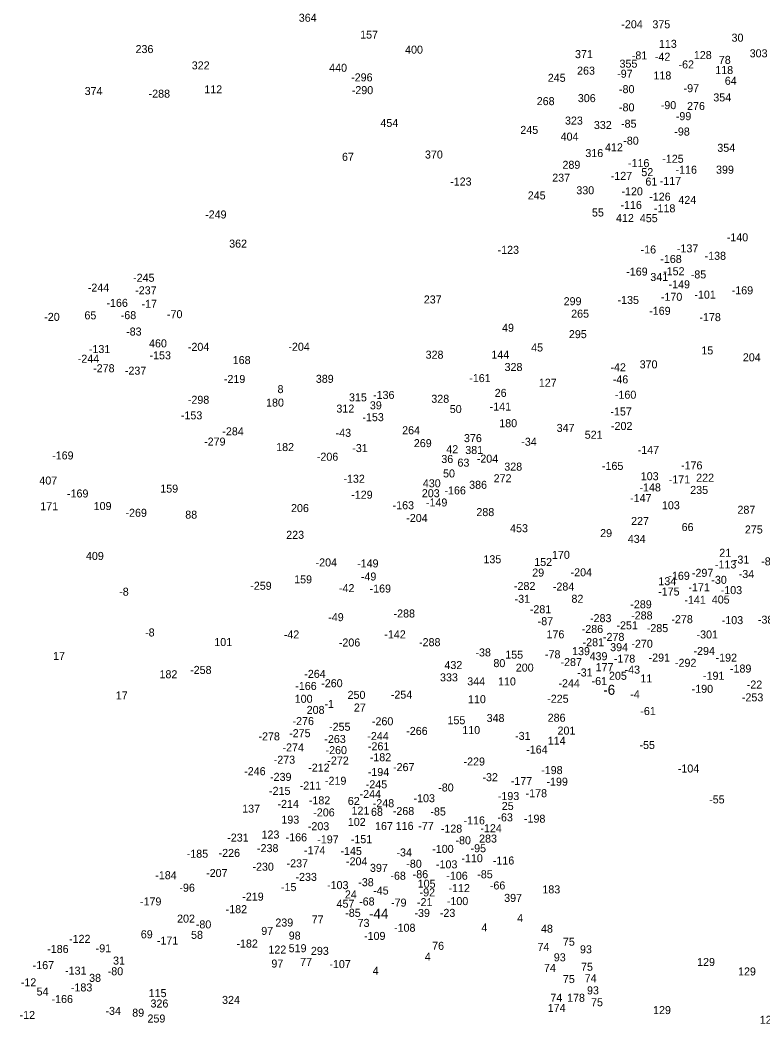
# Model space of a CAD drawing. Extents: x -784109 to -782312, y -974244 to -970866.
# Drawn here: x -783411 to -782876, y -973652 to -972930 of the extents above; entities that cross this region are included whole.
import ezdxf

# ---------------------------------------------------------------- set-up
doc = ezdxf.new("R2010")
doc.units = 0
doc.layers.add('Vrstva 24', color=7, linetype='Continuous')

msp = doc.modelspace()

# ---------------------------------------------------------------- texts
at = {"layer": 'Vrstva 24'}
for s, height, p in [('364', 5.76, (-783210.142, -972931.112)), ('-204', 5.76, (-782978.038, -972935.798)), ('375', 5.76, (-782955.695, -972935.832)), ('157', 5.76, (-783165.987, -972943.272)), ('30', 5.76, (-782898.749, -972945.472)), ('236', 5.76, (-783327.586, -972953.662)), ('400', 5.76, (-783133.642, -972954.082)), ('113', 5.76, (-782951.028, -972949.892)), ('371', 5.76, (-783011.377, -972957.292)), ('-81', 5.76, (-782970.508, -972958.198)), ('-42', 5.76, (-782953.917, -972959.17)), ('128', 5.76, (-782925.875, -972957.962)), ('78', 5.76, (-782907.905, -972961.422)), ('303', 5.76, (-782885.699, -972956.702)), ('322', 5.76, (-783287.163, -972965.402)), ('440', 5.76, (-783188.271, -972967.102)), ('355', 5.76, (-782979.353, -972964.152)), ('-62', 5.76, (-782936.887, -972964.714)), ('-296', 5.76, (-783172.478, -972974.024)), ('245', 5.76, (-783030.968, -972974.332)), ('263', 5.76, (-783009.896, -972969.182)), ('-97', 5.76, (-782981.043, -972971.402)), ('118', 5.76, (-782954.938, -972972.652)), ('118', 5.76, (-782910.468, -972968.742)), ('112', 5.76, (-783278.118, -972982.652)), ('-80', 5.76, (-782979.732, -972982.506)), ('-97', 5.76, (-782933.241, -972981.8)), ('64', 5.76, (-782903.602, -972976.472)), ('374', 5.76, (-783364.211, -972983.842)), ('-288', 5.76, (-783318.188, -972985.756)), ('-290', 5.76, (-783172.012, -972983.214)), ('306', 5.76, (-783009.353, -972988.952)), ('354', 5.76, (-782911.858, -972988.452)), ('268', 5.76, (-783038.926, -972991.132)), ('-80', 5.76, (-782979.726, -972995.558)), ('-90', 5.76, (-782949.682, -972993.988)), ('276', 5.76, (-782930.758, -972994.632)), ('-99', 5.76, (-782938.845, -973001.936)), ('454', 5.76, (-783151.404, -973006.832)), ('245', 5.76, (-783050.728, -973011.812)), ('323', 5.76, (-783018.593, -973005.112)), ('332', 5.76, (-782997.803, -973008.302)), ('-85', 5.76, (-782978.266, -973007.33)), ('404', 5.76, (-783021.721, -973016.642)), ('-98', 5.76, (-782939.931, -973013.002)), ('412', 5.76, (-782989.801, -973024.362)), ('-80', 5.76, (-782976.672, -973019.552)), ('354', 5.76, (-782908.978, -973024.702)), ('67', 5.76, (-783179.048, -973031.172)), ('370', 5.76, (-783119.351, -973029.532)), ('316', 5.76, (-783003.939, -973028.482)), ('-125', 5.76, (-782948.616, -973032.6)), ('289', 5.76, (-783020.406, -973036.932)), ('-116', 5.76, (-782973.256, -973035.712)), ('-116', 5.76, (-782939.048, -973040.482)), ('399', 5.76, (-782909.909, -973040.452)), ('237', 5.76, (-783027.775, -973046.202)), ('-127', 5.76, (-782985.683, -973044.9)), ('52', 5.76, (-782963.653, -973042.212)), ('-123', 5.76, (-783101.228, -973048.97)), ('330', 5.76, (-783010.439, -973055.262)), ('61', 5.76, (-782960.729, -973049.002)), ('-117', 5.76, (-782950.433, -973048.52)), ('245', 5.76, (-783045.378, -973058.972)), ('-120', 5.76, (-782977.968, -973056.04)), ('-126', 5.76, (-782957.99, -973059.88)), ('424', 5.76, (-782937.014, -973062.182)), ('-116', 5.76, (-782978.672, -973065.792)), ('-118', 5.76, (-782954.572, -973068.264)), ('-249', 5.76, (-783277.546, -973072.676)), ('55', 5.76, (-782999.173, -973071.252)), ('412', 5.76, (-782981.891, -973075.232)), ('455', 5.76, (-782964.728, -973075.332)), ('-140', 5.76, (-782902.196, -973089.126)), ('362', 5.76, (-783260.226, -973093.642)), ('-123', 5.76, (-783067.094, -973098.12)), ('-16', 5.76, (-782964.177, -973097.872)), ('-137', 5.76, (-782938.078, -973097.084)), ('-168', 5.76, (-782950.017, -973104.696)), ('-138', 5.76, (-782918.142, -973102.414)), ('-245', 5.76, (-783329.38, -973118.216)), ('-169', 5.76, (-782974.54, -973113.78)), ('341', 5.76, (-782957.191, -973117.652)), ('-152', 5.76, (-782947.978, -973113.526)), ('-85', 5.76, (-782928.095, -973115.81)), ('-244', 5.76, (-783361.966, -973125.324)), ('-237', 5.76, (-783327.859, -973127.258)), ('-149', 5.76, (-782944.059, -973122.93)), ('-169', 5.76, (-782898.638, -973127.254)), ('237', 5.76, (-783120.185, -973133.822)), ('-135', 5.76, (-782980.768, -973134.186)), ('-170', 5.76, (-782949.606, -973131.934)), ('-101', 5.76, (-782925.488, -973130.36)), ('-166', 5.76, (-783348.538, -973136.294)), ('-17', 5.76, (-783323.284, -973136.962)), ('299', 5.76, (-783019.559, -973135.092)), ('-169', 5.76, (-782958.022, -973142.012)), ('-20', 5.76, (-783393.296, -973146.356)), ('65', 5.76, (-783364.366, -973145.242)), ('-68', 5.76, (-783338.254, -973145.124)), ('-70', 5.76, (-783304.962, -973144.422)), ('265', 5.76, (-783014.146, -973144.052)), ('-178', 5.76, (-782921.876, -973146.552)), ('49', 5.76, (-783063.892, -973154.182)), ('-83', 5.76, (-783334.373, -973156.898)), ('295', 5.76, (-783015.786, -973158.782)), ('-131', 5.76, (-783361.19, -973169.52)), ('460', 5.76, (-783317.879, -973165.412)), ('-204', 5.76, (-783289.951, -973167.919)), ('-204', 5.76, (-783217.621, -973167.833)), ('45', 5.76, (-783042.938, -973168.392)), ('15', 5.76, (-782920.455, -973170.502)), ('-244', 5.76, (-783369.184, -973176.47)), ('-153', 5.76, (-783317.544, -973174.03)), ('168', 5.76, (-783257.669, -973177.442)), ('328', 5.76, (-783118.873, -973173.582)), ('144', 5.76, (-783071.567, -973173.542)), ('204', 5.76, (-782890.615, -973175.482)), ('-278', 5.76, (-783358.108, -973183.31)), ('-237', 5.76, (-783335.285, -973185.05)), ('328', 5.76, (-783062.053, -973182.442)), ('-42', 5.76, (-782985.908, -973182.632)), ('370', 5.76, (-782964.871, -973180.512)), ('-219', 5.76, (-783264.038, -973191.055)), ('389', 5.76, (-783197.876, -973190.942)), ('-161', 5.76, (-783087.484, -973190.414)), ('-46', 5.76, (-782984.218, -973191.334)), ('8', 5.76, (-783225.423, -973198.362)), ('127', 5.76, (-783037.407, -973193.732)), ('-298', 5.76, (-783289.967, -973206.006)), ('315', 5.76, (-783174.025, -973204.272)), ('-136', 5.76, (-783156.696, -973202.535)), ('328', 5.76, (-783114.763, -973205.302)), ('26', 5.76, (-783069.176, -973201.052)), ('-160', 5.76, (-782982.69, -973202.37)), ('180', 5.76, (-783233.682, -973208.042)), ('312', 5.76, (-783183.075, -973212.362)), ('39', 5.76, (-783158.976, -973209.992)), ('50', 5.76, (-783101.499, -973212.682)), ('-141', 5.76, (-783072.778, -973210.894)), ('-153', 5.76, (-783294.976, -973217.216)), ('-153', 5.76, (-783164.377, -973218.541)), ('-157', 5.76, (-782985.92, -973214.444)), ('264', 5.76, (-783135.752, -973227.952)), ('180', 5.76, (-783065.882, -973222.872)), ('347', 5.76, (-783024.591, -973226.272)), ('-202', 5.76, (-782985.502, -973224.872)), ('-284', 5.76, (-783265.149, -973228.736)), ('-43', 5.76, (-783183.634, -973229.797)), ('376', 5.76, (-783091.288, -973233.612)), ('521', 5.76, (-783004.395, -973231.182)), ('-279', 5.76, (-783278.279, -973236.096)), ('182', 5.76, (-783226.405, -973240.052)), ('-31', 5.76, (-783171.647, -973240.779)), ('269', 5.76, (-783127.349, -973237.212)), ('42', 5.76, (-783103.988, -973241.582)), ('381', 5.76, (-783090.345, -973242.152)), ('-34', 5.76, (-783050.038, -973236.218)), ('-147', 5.76, (-782966.27, -973242.089)), ('-169', 5.76, (-783387.614, -973246.07)), ('-206', 5.76, (-783197.141, -973246.989)), ('36', 5.76, (-783107.586, -973248.612)), ('-204', 5.76, (-783082.074, -973248.388)), ('63', 5.76, (-783095.946, -973251.242)), ('328', 5.76, (-783062.263, -973254.112)), ('-165', 5.76, (-782991.997, -973253.606)), ('-176', 5.76, (-782935.1, -973253.213)), ('407', 5.76, (-783396.797, -973264.112)), ('-132', 5.76, (-783178.013, -973262.843)), ('50', 5.76, (-783106.329, -973259.012)), ('272', 5.76, (-783069.915, -973262.492)), ('103', 5.76, (-782964.062, -973260.992)), ('-171', 5.76, (-782943.961, -973263.313)), ('222', 5.76, (-782924.193, -973262.092)), ('159', 5.76, (-783309.809, -973269.962)), ('430', 5.76, (-783120.875, -973266.112)), ('-166', 5.76, (-783105.324, -973271.228)), ('386', 5.76, (-783087.566, -973267.192)), ('-148', 5.76, (-782965.032, -973269.079)), ('235', 5.76, (-782928.483, -973270.892)), ('-169', 5.76, (-783376.92, -973273.434)), ('-129', 5.76, (-783172.404, -973274.323)), ('203', 5.76, (-783121.599, -973273.262)), ('-147', 5.76, (-782971.764, -973276.765)), ('171', 5.76, (-783396.15, -973282.642)), ('109', 5.76, (-783357.725, -973282.492)), ('206', 5.76, (-783215.723, -973283.952)), ('-163', 5.76, (-783142.623, -973281.898)), ('-149', 5.76, (-783118.643, -973279.892)), ('103', 5.76, (-782948.832, -973281.892)), ('287', 5.76, (-782894.495, -973285.142)), ('-269', 5.76, (-783334.836, -973287.334)), ('88', 5.76, (-783291.823, -973288.672)), ('-204', 5.76, (-783132.818, -973291.074)), ('288', 5.76, (-783082.343, -973286.842)), ('227', 5.76, (-782971.005, -973293.222)), ('453', 5.76, (-783058.078, -973298.432)), ('66', 5.76, (-782934.669, -973297.602)), ('275', 5.76, (-782889.145, -973299.342)), ('223', 5.76, (-783219.173, -973303.202)), ('29', 5.76, (-782993.276, -973301.932)), ('434', 5.76, (-782973.394, -973306.142)), ('409', 5.76, (-783363.289, -973318.382)), ('135', 5.76, (-783077.265, -973320.772)), ('170', 5.76, (-783027.964, -973317.592)), ('21', 5.76, (-782907.595, -973316.092)), ('-31', 5.76, (-782897.097, -973320.996)), ('-89', 5.76, (-782877.423, -973322.292)), ('-204', 5.76, (-783198.045, -973323.055)), ('-149', 5.76, (-783168.171, -973323.764)), ('152', 5.76, (-783040.735, -973322.732)), ('-113', 5.76, (-782910.694, -973324.515)), ('159', 5.76, (-783213.469, -973335.242)), ('-49', 5.76, (-783165.464, -973333.174)), ('29', 5.76, (-783042.156, -973330.352)), ('-204', 5.76, (-783014.566, -973330.148)), ('134', 5.76, (-782951.421, -973336.582)), ('-169', 5.76, (-782944.215, -973332.66)), ('-297', 5.76, (-782927.275, -973330.535)), ('-30', 5.76, (-782913.296, -973335.581)), ('-34', 5.76, (-782893.603, -973331.41)), ('-8', 5.76, (-783339.351, -973344.126)), ('-259', 5.76, (-783245.056, -973339.855)), ('-42', 5.76, (-783181.216, -973341.544)), ('-169', 5.76, (-783159.198, -973341.842)), ('-282', 5.76, (-783055.313, -973340.028)), ('-284', 5.76, (-783027.339, -973340.408)), ('-175', 5.76, (-782951.561, -973343.976)), ('-171', 5.76, (-782929.795, -973340.92)), ('-103', 5.76, (-782906.554, -973342.976)), ('-31', 5.76, (-783054.846, -973349.234)), ('82', 5.76, (-783013.943, -973349.202)), ('-141', 5.76, (-782932.698, -973349.958)), ('405', 5.76, (-782912.965, -973349.762)), ('-281', 5.76, (-783043.905, -973356.728)), ('-289', 5.76, (-782971.6, -973353.186)), ('-49', 5.76, (-783188.948, -973362.428)), ('-288', 5.76, (-783141.948, -973359.792)), ('-87', 5.76, (-783038.245, -973365.338)), ('-283', 5.76, (-783000.577, -973363.156)), ('-288', 5.76, (-782971.007, -973361.186)), ('-278', 5.76, (-782942.029, -973363.886)), ('-103', 5.76, (-782905.822, -973364.582)), ('-38', 5.76, (-782879.778, -973364.238)), ('-286', 5.76, (-783006.55, -973370.936)), ('-251', 5.76, (-782981.589, -973368.336)), ('-285', 5.76, (-782959.727, -973370.316)), ('-8', 5.76, (-783320.728, -973373.448)), ('101', 5.76, (-783270.925, -973380.342)), ('-42', 5.76, (-783220.94, -973374.898)), ('-142', 5.76, (-783148.586, -973374.826)), ('176', 5.76, (-783031.891, -973374.772)), ('-278', 5.76, (-782991.269, -973376.626)), ('-301', 5.76, (-782923.932, -973374.872)), ('-206', 5.76, (-783181.332, -973380.676)), ('-288', 5.76, (-783123.598, -973380.432)), ('139', 5.76, (-783013.479, -973386.882)), ('-281', 5.76, (-783005.916, -973380.468)), ('394', 5.76, (-782986.062, -973384.032)), ('-270', 5.76, (-782970.815, -973381.566)), ('-294', 5.76, (-782926.125, -973386.756)), ('17', 5.76, (-783386.897, -973390.342)), ('-38', 5.76, (-783083.027, -973387.807)), ('155', 5.76, (-783061.605, -973389.442)), ('-78', 5.76, (-783032.994, -973389.14)), ('-287', 5.76, (-783021.826, -973394.748)), ('439', 5.76, (-783000.892, -973390.542)), ('-178', 5.76, (-782983.468, -973392.278)), ('-291', 5.76, (-782958.443, -973391.526)), ('-192', 5.76, (-782910.228, -973391.578)), ('-258', 5.76, (-783288.313, -973400.405)), ('432', 5.76, (-783105.348, -973396.902)), ('80', 5.76, (-783070.089, -973395.512)), ('200', 5.76, (-783053.996, -973398.762)), ('177', 5.76, (-782996.549, -973398.422)), ('-43', 5.76, (-782975.718, -973400.18)), ('-292', 5.76, (-782939.47, -973395.266)), ('-189', 5.76, (-782899.888, -973399.414)), ('182', 5.76, (-783310.355, -973403.512)), ('-264', 5.76, (-783206.178, -973403.247)), ('333', 5.76, (-783108.503, -973405.762)), ('344', 5.76, (-783088.914, -973408.652)), ('110', 5.76, (-783066.765, -973408.692)), ('-31', 5.76, (-783009.859, -973402.24)), ('-61', 5.76, (-782999.45, -973408.404)), ('205', 5.76, (-782986.949, -973404.632)), ('11', 5.76, (-782964.358, -973406.512)), ('-191', 5.76, (-782919.304, -973404.608)), ('-166', 5.76, (-783212.661, -973411.952)), ('-260', 5.76, (-783194, -973409.987)), ('-244', 5.76, (-783023.318, -973409.994)), ('-6', 7.2, (-782991.056, -973415.427)), ('-190', 5.76, (-782927.449, -973414.002)), ('-22', 5.76, (-782887.815, -973410.925)), ('17', 5.76, (-783341.827, -973418.762)), ('100', 5.76, (-783213.059, -973421.162)), ('250', 5.76, (-783175.019, -973418.362)), ('-254', 5.76, (-783143.925, -973418.187)), ('110', 5.76, (-783088.375, -973421.452)), ('-225', 5.76, (-783031.392, -973421.146)), ('-4', 5.76, (-782971.615, -973417.884)), ('-253', 5.76, (-782891.315, -973420.155)), ('208', 5.76, (-783204.459, -973429.182)), ('-1', 5.76, (-783191.676, -973424.848)), ('27', 5.76, (-783170.475, -973427.452)), ('-61', 5.76, (-782964.398, -973430.008)), ('-276', 5.76, (-783214.645, -973437.207)), ('-260', 5.76, (-783157.52, -973437.357)), ('155', 5.76, (-783103.135, -973436.602)), ('348', 5.76, (-783074.968, -973435.012)), ('286', 5.76, (-783031.066, -973434.802)), ('-255', 5.76, (-783188.36, -973441.307)), ('-266', 5.76, (-783132.836, -973444.307)), ('110', 5.76, (-783092.495, -973443.692)), ('201', 5.76, (-783023.962, -973444.062)), ('-278', 5.76, (-783239.152, -973448.217)), ('-275', 5.76, (-783217.072, -973445.927)), ('-263', 5.76, (-783191.743, -973450.107)), ('-244', 5.76, (-783160.811, -973447.997)), ('-31', 5.76, (-783054.509, -973447.886)), ('114', 5.76, (-783030.993, -973451.312)), ('-274', 5.76, (-783221.868, -973456.197)), ('-260', 5.76, (-783190.89, -973458.097)), ('-261', 5.76, (-783160.396, -973455.357)), ('-164', 5.76, (-783046.51, -973457.684)), ('-55', 5.76, (-782965, -973454.43)), ('-273', 5.76, (-783228.162, -973465.017)), ('-272', 5.76, (-783189.596, -973465.639)), ('-182', 5.76, (-783159.062, -973463.227)), ('-229', 5.76, (-783091.598, -973466.296)), ('-246', 5.76, (-783249.423, -973473.275)), ('-212', 5.76, (-783203.356, -973470.719)), ('-194', 5.76, (-783160.488, -973473.865)), ('-267', 5.76, (-783142.325, -973470.327)), ('-198', 5.76, (-783035.734, -973472.494)), ('-104', 5.76, (-782937.415, -973471.338)), ('-239', 5.76, (-783230.803, -973477.357)), ('-219', 5.76, (-783191.304, -973480.157)), ('-32', 5.76, (-783077.991, -973477.58)), ('-177', 5.76, (-783057.595, -973480.35)), ('-199', 5.76, (-783031.93, -973480.808)), ('-215', 5.76, (-783231.55, -973487.425)), ('-211', 5.76, (-783209.476, -973483.607)), ('-245', 5.76, (-783161.971, -973482.715)), ('-80', 5.76, (-783109.822, -973485.004)), ('-182', 5.76, (-783202.906, -973494.267)), ('62', 5.76, (-783174.856, -973494.692)), ('-244', 5.76, (-783166.371, -973489.707)), ('-103', 5.76, (-783127.586, -973492.732)), ('-193', 5.76, (-783066.923, -973491.172)), ('-178', 5.76, (-783046.916, -973489.122)), ('-55', 5.76, (-782914.85, -973493.584)), ('137', 5.76, (-783250.857, -973500.252)), ('-214', 5.76, (-783225.47, -973496.815)), ('-206', 5.76, (-783199.716, -973502.917)), ('121', 5.76, (-783172.188, -973501.632)), ('68', 5.76, (-783158.166, -973502.532)), ('-248', 5.76, (-783156.923, -973496.303)), ('-268', 5.76, (-783142.501, -973501.943)), ('-85', 5.76, (-783115.453, -973502.26)), ('25', 5.76, (-783064.083, -973498.292)), ('193', 5.76, (-783222.659, -973508.132)), ('102', 5.76, (-783174.852, -973509.782)), ('-116', 5.76, (-783091.608, -973508.674)), ('-63', 5.76, (-783067.224, -973506.484)), ('-198', 5.76, (-783048.124, -973507.448)), ('-203', 5.76, (-783203.628, -973512.867)), ('167', 5.76, (-783155.281, -973512.752)), ('116', 5.76, (-783140.391, -973512.622)), ('-77', 5.76, (-783124.155, -973512.622)), ('-128', 5.76, (-783107.96, -973514.584)), ('-124', 5.76, (-783079.47, -973514.314)), ('-231', 5.76, (-783261.616, -973521.058)), ('123', 5.76, (-783236.935, -973518.842)), ('-166', 5.76, (-783219.595, -973520.841)), ('-197', 5.76, (-783196.838, -973522.343)), ('-151', 5.76, (-783172.7, -973522.189)), ('-80', 5.76, (-783097.402, -973522.982)), ('283', 5.76, (-783080.383, -973521.762)), ('-226', 5.76, (-783267.823, -973532.081)), ('-238', 5.76, (-783240.189, -973528.642)), ('-174', 5.76, (-783206.37, -973530.153)), ('-145', 5.76, (-783180.174, -973530.717)), ('-34', 5.76, (-783139.859, -973531.733)), ('-100', 5.76, (-783114.117, -973529.174)), ('-95', 5.76, (-783086.534, -973528.718)), ('-185', 5.76, (-783290.779, -973532.669)), ('-204', 5.76, (-783176.158, -973538.123)), ('-110', 5.76, (-783093.147, -973535.932)), ('-116', 5.76, (-783070.514, -973537.556)), ('-207', 5.76, (-783276.81, -973546.535)), ('-230', 5.76, (-783243.47, -973542.004)), ('-237', 5.76, (-783218.901, -973539.548)), ('397', 5.76, (-783158.908, -973542.822)), ('-80', 5.76, (-783132.778, -973539.866)), ('-103', 5.76, (-783111.44, -973540.318)), ('-184', 5.76, (-783313.401, -973548.117)), ('-233', 5.76, (-783212.519, -973549.34)), ('-38', 5.76, (-783167.361, -973553.145)), ('-68', 5.76, (-783144.219, -973548.517)), ('-86', 5.76, (-783128.181, -973547.392)), ('-106', 5.76, (-783103.986, -973548.508)), ('-85', 5.76, (-783081.729, -973547.446)), ('-96', 5.76, (-783296.032, -973557.125)), ('-15', 5.76, (-783222.974, -973556.692)), ('-103', 5.76, (-783189.792, -973555.242)), ('-45', 5.76, (-783156.606, -973559.133)), ('105', 5.76, (-783124.572, -973554.222)), ('-92', 5.76, (-783123.205, -973560.472)), ('-112', 5.76, (-783102.424, -973557.398)), ('-66', 5.76, (-783072.656, -973555.488)), ('183', 5.76, (-783034.875, -973558.322)), ('-179', 5.76, (-783324.399, -973566.985)), ('-219', 5.76, (-783250.808, -973563.539)), ('24', 5.76, (-783176.968, -973561.932)), ('-68', 5.76, (-783166.733, -973567.019)), ('-79', 5.76, (-783143.759, -973567.827)), ('-21', 5.76, (-783125.081, -973567.51)), ('-100', 5.76, (-783103.605, -973566.744)), ('397', 5.76, (-783062.348, -973564.442)), ('-182', 5.76, (-783262.739, -973572.559)), ('457', 5.76, (-783182.961, -973568.622)), ('-85', 5.76, (-783176.73, -973575.189)), ('-44', 7.2, (-783159.633, -973576.571)), ('-39', 5.76, (-783126.923, -973575.274)), ('-23', 5.76, (-783108.647, -973575.234)), ('202', 5.76, (-783297.699, -973579.372)), ('239', 5.76, (-783226.996, -973582.172)), ('77', 5.76, (-783200.877, -973579.982)), ('73', 5.76, (-783167.805, -973582.442)), ('4', 5.76, (-783052.998, -973578.952)), ('-80', 5.76, (-783284.223, -973583.501)), ('97', 5.76, (-783237.148, -973588.212)), ('-108', 5.76, (-783141.6, -973585.942)), ('4', 5.76, (-783078.718, -973585.742)), ('48', 5.76, (-783035.858, -973586.602)), ('-122', 5.76, (-783375.427, -973593.911)), ('69', 5.76, (-783323.809, -973590.642)), ('-171', 5.76, (-783312.254, -973595.159)), ('58', 5.76, (-783287.653, -973591.042)), ('98', 5.76, (-783217.366, -973591.562)), ('-109', 5.76, (-783163.188, -973591.804)), ('75', 5.76, (-783020.105, -973595.982)), ('-186', 5.76, (-783391.18, -973601.195)), ('-91', 5.76, (-783356.28, -973600.731)), ('-182', 5.76, (-783254.991, -973597.277)), ('122', 5.76, (-783231.995, -973601.602)), ('519', 5.76, (-783217.409, -973600.652)), ('293', 5.76, (-783201.406, -973602.572)), ('76', 5.76, (-783114.178, -973598.922)), ('74', 5.76, (-783038.351, -973599.682)), ('93', 5.76, (-783007.806, -973601.442)), ('31', 5.76, (-783343.755, -973609.552)), ('77', 5.76, (-783209.107, -973610.462)), ('4', 5.76, (-783119.468, -973606.752)), ('93', 5.76, (-783026.636, -973607.202)), ('129', 5.76, (-782923.519, -973610.572)), ('-167', 5.76, (-783401.623, -973612.837)), ('-131', 5.76, (-783378.299, -973616.781)), ('-80', 5.76, (-783347.617, -973617.227)), ('97', 5.76, (-783229.838, -973611.692)), ('-107', 5.76, (-783188.13, -973612.07)), ('4', 5.76, (-783156.898, -973616.812)), ('74', 5.76, (-783033.721, -973614.822)), ('75', 5.76, (-783007.035, -973614.002)), ('129', 5.76, (-782894.079, -973617.372)), ('-12', 5.76, (-783410.152, -973625.216)), ('38', 5.76, (-783361.013, -973621.982)), ('75', 5.76, (-783020.105, -973622.862)), ('74', 5.76, (-783004.391, -973622.232)), ('54', 5.76, (-783398.778, -973631.832)), ('-183', 5.76, (-783374.117, -973628.877)), ('115', 5.76, (-783318.148, -973632.972)), ('93', 5.76, (-783002.756, -973630.992)), ('-166', 5.76, (-783388.04, -973637.237)), ('326', 5.76, (-783316.826, -973640.442)), ('324', 5.76, (-783265.338, -973637.862)), ('74', 5.76, (-783029.081, -973636.232)), ('178', 5.76, (-783017.087, -973636.322)), ('75', 5.76, (-782999.825, -973639.532)), ('-34', 5.76, (-783349.242, -973645.753)), ('89', 5.76, (-783329.976, -973647.072)), ('174', 5.76, (-783031.013, -973643.632)), ('129', 5.76, (-782955.219, -973645.172)), ('-12', 5.76, (-783411.018, -973648.697)), ('259', 5.76, (-783318.996, -973651.242)), ('129', 5.76, (-782878.439, -973652.172))]:
    msp.add_text(s, height=height, dxfattribs=at).set_placement(p)

doc.saveas('drawing.dxf')
